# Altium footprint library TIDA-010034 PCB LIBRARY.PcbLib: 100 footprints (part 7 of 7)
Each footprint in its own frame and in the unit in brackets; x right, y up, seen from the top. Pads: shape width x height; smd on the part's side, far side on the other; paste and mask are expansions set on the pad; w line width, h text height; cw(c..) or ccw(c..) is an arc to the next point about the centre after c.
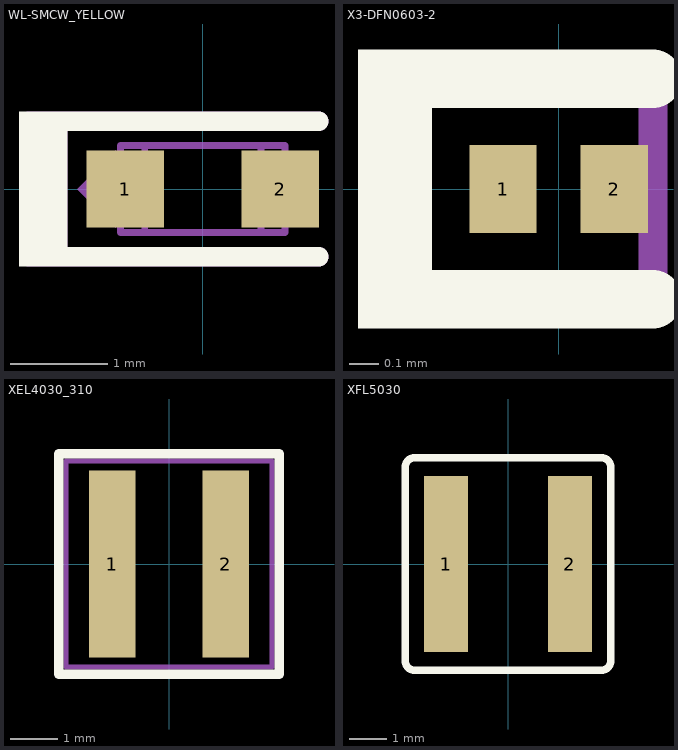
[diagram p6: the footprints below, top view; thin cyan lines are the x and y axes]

## WL-SMCW_YELLOW [mm] "WURTH"
height 0.8
pads (2):
  rect 0.8x0.8 smd: 1(-0.8,0) 2(0.8,0)
Top Overlay:
  rectangle: -1.9,-0.8 -1.4,0.8
  lines w0.2: -1.6,-0.7 1.2,-0.7 ; -1.6,0.7 1.2,0.7
Mechanical 5:
  region: -0.9,-0.4 -0.9,0.4 -1.3,0
  lines w0.2: -1.65,-0.7 -1.65,0.55 ; 1.2,-0.7 -1.5,-0.7 ; 1.2,0.7 -1.5,0.7 ; -1.5,-0.7 -1.5,0.7 ; -1.5,-0.7 -1.8,-0.7 -1.8,0.7 -1.5,0.7
  text ".Designator" at -0.8,-0.3 h0.45
Mechanical 13:
  lines w0.07: -0.6,-0.45 -0.6,0.45 ; 0.6,-0.45 0.6,0.45 ; -0.85,-0.45 -0.85,0.45 0.85,0.45 0.85,-0.45 -0.85,-0.45
3D body: height 0.36, standoff 0.35, extent -0.599,-0.449 0.599,0.449
3D body: height 0.35, standoff 0, extent -0.849,-0.449 -0.601,0.449
3D body: height 0.35, standoff 0, extent -0.599,-0.449 0.599,0.449
3D body: height 0.35, standoff 0, extent 0.601,-0.449 0.849,0.449
3D body: height 0.8, standoff 0.35, extent -0.599,-0.449 0.599,0.449

## X3-DFN0603-2 [mm] "SMD, 2-Leads, Body 0.62x0.32mm"
height 0.35
pads (2):
  rect 0.23x0.3 smd mask+0.102: 1(-0.19,0) 2(0.19,0)
Top Overlay:
  rectangle: -0.686,-0.478 -0.482,0.478
  lines w0.1: -0.482,-0.3 -0.482,0.327
  lines w0.2: -0.482,-0.378 0.323,-0.378 ; -0.482,0.378 0.323,0.378
Top Solder:
  rectangle: -0.075,-0.2 0.075,0.2
Mechanical 5:
  rectangle: -0.686,-0.428 -0.482,0.428
  lines w0.1: -0.482,-0.378 0.323,-0.378 0.323,0.378 -0.482,0.378 -0.482,-0.378
  text ".Designator" at -0.406,-0.051 h0.15
3D body: height 0.35, standoff 0, extent -0.323,-0.172 0.323,0.172
3D body: height 0.35, standoff 0.35, extent -0.323,-0.172 -0.152,0.172

## XEL4030_310 [mm] "SMD, 2-Leads, Body 4x4mm, Pitch 2.37mm"
height 3.1
pads (2):
  rect 0.98x3.9 smd: 1(-1.185,0) 2(1.185,0)
Top Overlay:
  lines w0.2: -2.3,-2.3 2.3,-2.3 2.3,2.3 -2.3,2.3 -2.3,-2.3
Mechanical 5:
  lines w0.1: -2.15,-2.15 -2.15,2.15 2.15,2.15 2.15,-2.15 -2.15,-2.15
  text ".Designator" at -2,-0.7 h1.85
3D body: height 3.1, standoff 0, extent -2.149,-2.149 2.149,2.149

## XFL5030 [mm] "SMD, 2-Leads, Body 5.48x5.28mm"
height 3.1
pads (2):
  rect 1.18x4.7 smd: 1(-1.655,0) 2(1.655,0)
Top Overlay:
  lines w0.2: -2.74,-2.59 ccw(c-2.49,-2.59) -2.49,-2.84 2.49,-2.84 ccw(c2.49,-2.59) 2.74,-2.59 2.74,2.59 ccw(c2.49,2.59) 2.49,2.84 -2.49,2.84 ccw(c-2.49,2.59) -2.74,2.59 -2.74,-2.59
Mechanical 5:
  lines w0.1: -2.74,-2.59 ccw(c-2.49,-2.59) -2.49,-2.84 2.49,-2.84 ccw(c2.49,-2.59) 2.74,-2.59 2.74,2.59 ccw(c2.49,2.59) 2.49,2.84 -2.49,2.84 ccw(c-2.49,2.59) -2.74,2.59 -2.74,-2.59
  text ".Designator" at -2,-0.7 h1.85
3D body "Coilcraft-XFL5030.stp": height 3.1, standoff 0, extent -2.74,-2.84 2.74,2.84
